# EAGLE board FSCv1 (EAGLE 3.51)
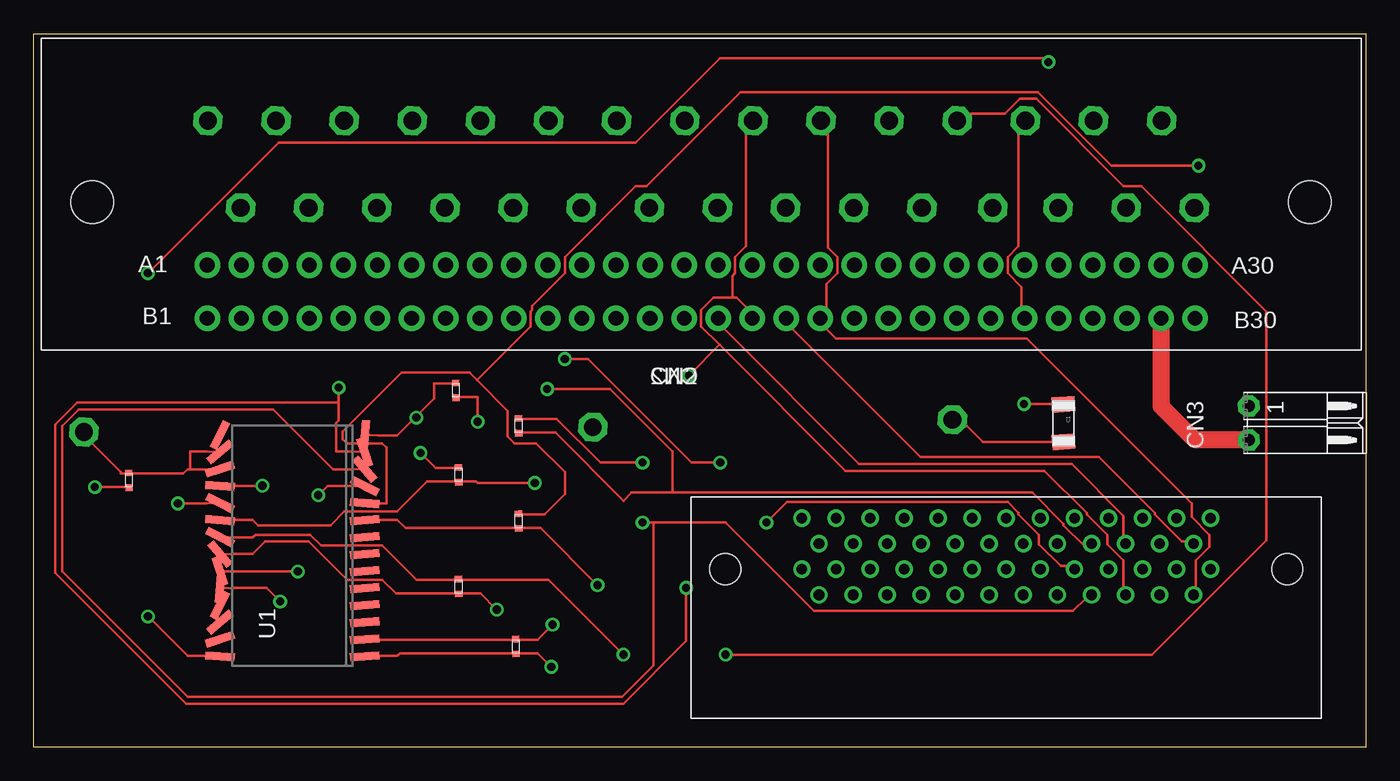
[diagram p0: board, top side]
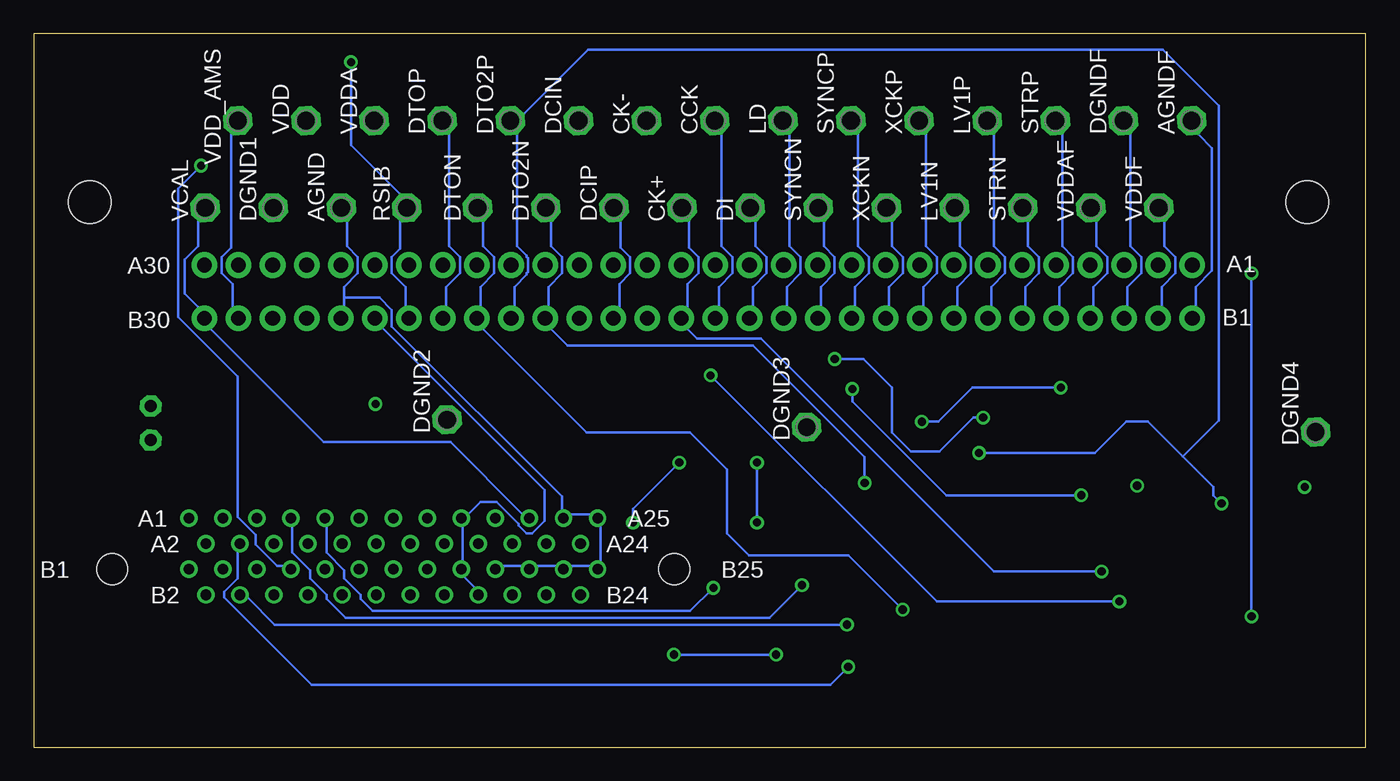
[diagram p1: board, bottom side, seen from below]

Size 99.36 x 53.24 mm. Coordinates in mm from the lower left corner, seen from the top.
Outline: 0,53.24 99.36,53.24 99.36,0 0,0 0,53.24
Copper layers used: Top, Bottom

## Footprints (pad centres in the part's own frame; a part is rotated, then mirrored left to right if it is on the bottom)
-13 = drill 1.321 pad 2.159 octagon:  0,0
06 = smd 1.15 x 1.7 rotated 4.3:  -1.4,0 | smd 1.15 x 1.7 rotated 4.4:  1.4,0
02 = smd 0.5 x 0.55 rotated 4.3:  -0.55,0 | smd 0.5 x 0.55 rotated 4.4:  0.55,0
0LE050 = drill 0.787 pad 1.194 round:  15.24,2.857;  13.97,0.953;  12.7,2.857;  11.43,0.953;  10.16,2.857;  15.24,-0.953;  13.97,-2.857;  12.7,-0.953;  11.43,-2.857;  10.16,-0.953;  8.89,-2.857;  8.89,0.953;  7.62,2.857;  6.35,0.953;  5.08,2.857;  3.81,0.953;  2.54,2.857;  7.62,-0.953;  6.35,-2.857;  5.08,-0.953;  3.81,-2.857;  2.54,-0.953;  1.27,-2.857;  1.27,0.953;  0,2.857;  -1.27,0.953;  -2.54,2.857;  -3.81,0.953;  -5.08,2.857;  0,-0.953;  -1.27,-2.857;  -2.54,-0.953;  -3.81,-2.857;  -5.08,-0.953;  -6.35,-2.857;  -6.35,0.953;  -7.62,2.857;  -8.89,0.953;  -10.16,2.857;  -11.43,0.953;  -12.7,2.857;  -7.62,-0.953;  -8.89,-2.857;  -10.16,-0.953;  -11.43,-2.857;  -12.7,-0.953;  -13.97,-2.857;  -13.97,0.953;  -15.24,2.857;  -15.24,-0.953 | hole 2.311: 20.955,-0.953; -20.955,-0.953
30LP = drill 1.092 pad 1.905 round:  36.83,3.962;  36.83,0;  34.29,3.962;  34.29,0;  31.75,3.962;  31.75,0;  29.21,3.962;  29.21,0;  26.67,3.962;  26.67,0;  24.13,3.962;  24.13,0;  21.59,3.962;  21.59,0;  19.05,3.962;  19.05,0;  16.51,3.962;  16.51,0;  13.97,3.962;  13.97,0;  11.43,3.962;  11.43,0;  8.89,3.962;  8.89,0;  6.35,3.962;  6.35,0;  3.81,3.962;  3.81,0;  1.27,3.962;  1.27,0;  -1.27,3.962;  -1.27,0;  -3.81,3.962;  -3.81,0;  -6.35,3.962;  -6.35,0;  -8.89,3.962;  -8.89,0;  -11.43,3.962;  -11.43,0;  -13.97,3.962;  -13.97,0;  -16.51,3.962;  -16.51,0;  -19.05,3.962;  -19.05,0;  -21.59,3.962;  -21.59,0;  -24.13,3.962;  -24.13,0;  -26.67,3.962;  -26.67,0;  -29.21,3.962;  -29.21,0;  -31.75,3.962;  -31.75,0;  -34.29,3.962;  -34.29,0;  -36.83,3.962;  -36.83,0 | hole 3.175: -45.403,-4.699; 45.403,-4.699
PA = drill 0.914 pad 1.6 octagon:  -1.27,0;  1.27,0
28X = smd 0.6 x 2.2 rotated 4.4:  -6.985,-5.4;  1.905,5.4 | smd 0.6 x 2.2 rotated 71.8:  6.985,-5.4 | smd 0.6 x 2.2 rotated 4.3:  -8.255,-5.4;  3.175,-5.4 | smd 0.6 x 2.2 rotated 4.5:  -5.715,-5.4 | smd 0.6 x 2.2 rotated 4.6:  -4.445,-5.4 | smd 0.6 x 2.2 rotated 94.3:  8.255,-5.4 | smd 0.6 x 2.2 rotated 49.3:  5.715,-5.4 | smd 0.6 x 2.2 rotated 26.8:  4.445,-5.4 | smd 0.6 x 2.2 rotated 4.7:  -1.905,-5.4;  -3.175,-5.4 | smd 0.6 x 2.2 rotated 5:  1.905,-5.4 | smd 0.6 x 2.2 rotated 4.8:  -0.635,-5.4 | smd 0.6 x 2.2 rotated 4.9:  0.635,-5.4 | smd 0.6 x 2.2 rotated 116.8:  8.255,5.4 | smd 0.6 x 2.2 rotated 139.3:  6.985,5.4 | smd 0.6 x 2.2 rotated 161.8:  5.715,5.4 | smd 0.6 x 2.2 rotated 184.3:  4.445,5.4 | smd 0.6 x 2.2 rotated 206.8:  3.175,5.4 | smd 0.6 x 2.2 rotated 26.9:  0.635,5.4 | smd 0.6 x 2.2 rotated 49.4:  -0.635,5.4 | smd 0.6 x 2.2 rotated 71.9:  -1.905,5.4 | smd 0.6 x 2.2 rotated 94.4:  -3.175,5.4 | smd 0.6 x 2.2 rotated 116.9:  -4.445,5.4 | smd 0.6 x 2.2 rotated 139.4:  -5.715,5.4 | smd 0.6 x 2.2 rotated 161.9:  -6.985,5.4 | smd 0.6 x 2.2 rotated 184.4:  -8.255,5.4

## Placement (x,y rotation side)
AGND  B1,27  [-13]  76.4,40.23 90 bottom
AGNDF  B1,27  [-13]  13,46.74 90 bottom
C1  4.7  [06]  76.81,24.18 270 top
C2  0.1  [02]  7.11,19.91 90 top
CCK  B1,27  [-13]  48.56,46.74 90 bottom
CK+  B1,27  [-13]  51,40.23 90 bottom
CK-  B1,27  [-13]  53.64,46.74 90 bottom
CN1  P50LE050  [0LE050]  72.54,14.22 0 top
CN2  EZC30DRAS  [30LP]  49.78,35.97 180 top
CN3  AMS PWR  [PA]  90.63,24.18 270 top
DCIN  B1,27  [-13]  58.72,46.74 90 bottom
DCIP  B1,27  [-13]  56.08,40.23 90 bottom
DGND1  B1,27  [-13]  81.48,40.23 90 bottom
DGND2  B1,27  [-13]  68.53,24.43 90 bottom
DGND3  B1,27  [-13]  41.71,23.88 90 bottom
DGND4  B1,27  [-13]  3.76,23.52 90 bottom
DGNDF  B1,27  [-13]  18.08,46.74 90 bottom
DI  B1,27  [-13]  45.92,40.23 90 bottom
DTO2N  B1,27  [-13]  61.16,40.23 90 bottom
DTO2P  B1,27  [-13]  63.8,46.74 90 bottom
DTON  B1,27  [-13]  66.24,40.23 90 bottom
DTOP  B1,27  [-13]  68.88,46.74 90 bottom
LD  B1,27  [-13]  43.48,46.74 90 bottom
LV1N  B1,27  [-13]  30.68,40.23 90 bottom
LV1P  B1,27  [-13]  28.24,46.74 90 bottom
R1  110  [02]  35.97,7.52 270 top
R2  110  [02]  31.7,11.99 270 top
R3  110  [02]  31.7,20.32 270 top
R4  110  [02]  31.5,26.62 90 top
R5  110  [02]  36.17,23.98 90 top
R6  110  [02]  36.17,16.87 90 top
RSIB  B1,27  [-13]  71.53,40.23 90 bottom
STRN  B1,27  [-13]  25.6,40.23 90 bottom
STRP  B1,27  [-13]  23.16,46.74 90 bottom
SYNCN  B1,27  [-13]  40.84,40.23 90 bottom
SYNCP  B1,27  [-13]  38.4,46.74 90 bottom
U1  IBM_BUF  [28X]  19.3,15.04 90 top
VCAL  B1,27  [-13]  86.56,40.23 90 bottom
VDD  B1,27  [-13]  79.04,46.74 90 bottom
VDD_AMS  B1,27  [-13]  84.12,46.74 90 bottom
VDDA  B1,27  [-13]  73.96,46.74 90 bottom
VDDAF  B1,27  [-13]  20.52,40.23 90 bottom
VDDF  B1,27  [-13]  15.44,40.23 90 bottom
XCKN  B1,27  [-13]  35.76,40.23 90 bottom
XCKP  B1,27  [-13]  33.32,46.74 90 bottom

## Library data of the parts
AGND AGNDF CCK CK+ CK- DCIN DCIP DGND1-DGND4 DGNDF DI DTO2N DTO2P DTON DTOP LD LV1N LV1P RSIB STRN STRP SYNCN SYNCP VCAL VDD VDD_AMS VDDA VDDAF VDDF XCKN XCKP = TESTPAD
C1 C2 R1-R6 = 1X
CN1 CN2 = CONNECT
CN3 = CONQUICK
U1 = IPC-SMD

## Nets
AGND: AGND. CN1. CN2.
CCK: CCK. CN2.
CK+: CK+. CN1. CN2. U1.
CK-: CK-. CN1. CN2. U1.
CKR+: CN1. R6. U1.
CKR-: CN1. R6. U1.
DCIN: CN1. CN2. DCIN.
DCIP: CN1. CN2. DCIP.
DGND: C1. C2. CN1. CN2. CN3. DGND1. DGND2. DGND3. DGND4. U1.
DI: CN2. DI.
DTO2+: CN1. R4. U1.
DTO2-: CN1. R4. U1.
DTO2N: CN2. DTO2N. R3. U1.
DTO2P: CN2. DTO2P. R3. U1.
DTO+: CN1. R5. U1.
DTO-: CN1. R5. U1.
DTON: CN2. DTON. R2. U1.
DTOP: CN2. DTOP. R2. U1.
LD: CN2. LD.
N$1: CN2. XCKP.
N$2: CN2. LV1N.
N$3: CN2. LV1P.
N$4: CN2. STRN.
N$5: CN2. XCKN.
N$6: CN2. STRP.
N$9: CN2. VDDAF.
N$10: CN2. DGNDF.
N$11: CN2. SYNCP.
N$12: CN2. VDDF.
N$13: AGNDF. CN2.
RSIB: CN2. RSIB. U1.
RSTB+: CN1. R1. U1.
RSTB-: CN1. R1. U1.
SYNCN: CN2. SYNCN.
VCAL: CN1. CN2. VCAL.
VDD: C1. C2. CN1. CN2. U1. VDD.
VDD_AMS: CN2. CN3. VDD_AMS.
VDDA: CN1. CN2. VDDA.

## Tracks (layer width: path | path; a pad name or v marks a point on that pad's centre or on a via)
AGND
  Bottom 0.203: 76.2,33.53 76.2,34.34 75.18,35.36 75.18,36.58 76,37.39 76,39.22 AGND. | 76.2,33.53 76.2,32.92 76.45,32 | 64.92,13.27 64.41,13.51 62.89,13.51 62.38,13.27 61.87,13.51 60.35,13.51 59.84,13.27 59.33,13.51 57.81,13.51 CN1. 57.1,13.82 57.1,16.56 57.3,17.08 57.81,17.37 59.33,17.37 59.84,17.08 59.94,17.68 59.94,18.69 72.64,31.39 72.64,32.61 73.56,33.53 76.2,33.53
CCK
  Bottom 0.203: 48.51,32 48.26,32.92 48.26,34.34 47.24,35.36 47.24,36.58 48.06,37.39 48.06,45.72 CCK.
CK+  (via drill 0.61 pad 1.02)
  Top 0.203: 81.43,15.18 81.28,15.75 81.28,17.27 77.42,21.13 61.57,21.13 51.51,31.19 51.05,32 | v19.71,13.11 14.94,13.11 13.9,13.13
  Bottom 0.203: v19.71,13.11 27.74,13.11 45.11,30.48 49.89,30.48 50.6,31.19 51.05,32 50.6,32.82 50.6,34.54 49.78,35.36 49.78,36.58 50.49,37.29 50.49,39.22 CK+.
CK-  (via drill 0.61 pad 1.02)
  Top 0.203: 51.16,30.02 49.78,31.39 49.78,32.61 50.7,33.53 52.12,33.53 | 51.16,30.02 60.55,20.62 75.39,20.62 78.54,17.48 78.54,17.37 80.06,15.85 80.06,15.14 81.28,13.92 81.28,11.89 81.43,11.37 | 52.12,33.53 52.43,33.53 53.14,32.82 53.59,32 | v18.39,10.87 17.37,11.89 14.94,11.89 13.9,11.86 | v48.87,27.74 51.16,30.02 | CK-. 53.14,45.72 53.14,37.39 52.32,36.58 52.32,35.36 52.12,35.15 52.12,33.53
  Bottom 0.203: v18.39,10.87 32,10.87 v48.87,27.74
CKR+  (via drill 0.61 pad 1.02)
  Top 0.203: 24.7,16.94 25.7,16.97 27.13,16.97 27.74,16.36 35.97,16.36 36.17,16.32 36.37,16.36 37.8,16.36 v42.06,12.09
  Bottom 0.203: v42.06,12.09 44.5,9.65 76.1,9.65 77.52,11.07 77.52,11.38 78.74,12.6 78.74,13.21 80.06,14.53 80.06,16.56 80.16,17.08
CKR-  (via drill 0.61 pad 1.02)
  Top 0.203: 33.07,27.38 32.51,27.94 27.43,27.94 23.06,23.57 23.06,22.96 23.37,22.66 26.01,22.66 26.31,22.35 26.31,18.19 25.7,18.19 24.7,18.21 | 33.07,27.38 35.36,25.09 35.36,23.16 35.87,22.66 37.49,22.66 39.62,20.52 39.62,18.9 38.1,17.37 36.37,17.37 R6. | v86.87,43.38 80.37,43.38 74.88,48.87 52.73,48.87 45.72,41.86 44.91,41.86 39.62,36.58 39.62,35.36 37.19,32.92 37.19,32.61 37.08,32.51 37.08,31.39 33.07,27.38
  Bottom 0.203: v86.87,43.38 88.59,41.66 88.59,32.11 84.12,27.64 84.12,17.17 82.8,15.85 82.8,15.14 81.18,13.51 80.67,13.51 80.16,13.27
DCIN
  Top 0.203: 86.51,11.37 86.67,11.89 86.67,13.92 87.68,14.94 87.68,15.85 86.36,17.17 86.36,18.19 74.07,30.48 59.84,30.48 59.13,31.19 58.67,32 59.13,32.82 59.13,34.54 59.94,35.36 59.94,36.58 59.23,37.29 59.23,45.72 DCIN.
DCIP
  Top 0.203: 86.51,15.18 85.95,15.34 85.65,15.34 83.62,17.37 83.62,17.48 79.45,21.64 66.14,21.64 56.59,31.19 56.13,32
  Bottom 0.203: DCIP. 55.58,39.22 55.58,37.29 54.86,36.58 54.86,35.36 55.68,34.54 55.68,32.82 56.13,32
DGND
  Top 0.203: 11.68,20.73 12.9,20.73 13.9,20.75 | 11.68,20.73 11.48,20.73 11.18,20.42 7.32,20.42 C2. 6.91,20.42 6.5,20.42 6.5,20.52 4.37,22.66 DGND4. | 13.9,22.02 12.9,22.05 11.68,22.05 11.68,20.73 | C1. 76,22.76 70.81,22.76 69.6,23.98 DGND2.
DI
  Bottom 0.203: 45.97,32 45.72,32.92 45.72,34.34 44.7,35.36 44.7,36.58 45.52,37.39 45.52,39.22 DI.
DTO2+  (via drill 0.61 pad 1.02)
  Top 0.203: v33.12,24.28 33.12,26.11 31.7,26.11 31.5,26.07 | 22.76,25.7 22.76,24.38 22.55,24.18 22.55,22.05 23.67,22.05 24.7,22.02 | 22.76,25.7 v22.76,26.82 | v48.67,11.89 48.67,7.92 43.99,3.25 11.38,3.25 1.63,13.01 1.63,24.08 3.25,25.7 22.76,25.7
  Bottom 0.203: v33.12,24.28 31.9,24.28 29.36,26.82 v22.76,26.82 | v48.67,11.89 50.39,10.16 74.07,10.16 74.98,11.07 74.98,11.38 76.2,12.6 76.2,13.21 77.52,14.53 77.52,16.56 77.62,17.08
DTO2-  (via drill 0.61 pad 1.02)
  Top 0.203: 28.5,24.64 27.13,23.27 25.7,23.27 24.7,23.29 | 28.5,24.64 29.87,26.01 29.87,27.13 31.29,27.13 R4. | v54.66,16.76 56.19,18.29 72.64,18.29 73.46,17.48 73.46,17.37 74.98,15.85 74.98,15.14 76.61,13.51 77.11,13.51 77.62,13.27 | v51.21,21.23 49.07,21.23 41.35,28.96 v39.62,28.96 | 28.5,24.64 v28.55,24.59
  Bottom 0.203: v54.66,16.76 54.66,17.78 v51.21,21.23 | v39.62,28.96 37.49,28.96 35.36,26.82 35.36,23.47 33.93,22.05 31.8,22.05 29.26,24.59 v28.55,24.59
DTO2N  (via drill 0.61 pad 1.02)
  Top 0.203: 13.9,16.94 14.94,16.97 16.36,16.97 16.76,16.56 22.15,16.56 23.16,17.58 27.13,17.58 29.36,19.81 31.5,19.81 R3. 31.9,19.81 33.02,19.81 33.12,19.71 v37.39,19.71
  Bottom 0.203: DTO2N. 60.76,39.22 60.76,37.39 59.94,36.58 59.94,35.36 60.96,34.34 60.96,32.92 61.21,32 60.76,31.19 59.54,29.97 45.72,29.97 37.39,21.64 v37.39,19.71
DTO2P  (via drill 0.61 pad 1.02)
  Top 0.203: v28.85,21.95 29.97,20.83 31.5,20.83 31.7,20.87 | v10.77,18.19 12.9,18.19 13.9,18.21
  Bottom 0.203: 63.75,32 63.5,32.92 63.5,34.34 62.59,35.26 62.59,35.36 62.48,35.46 62.48,36.47 62.59,36.58 62.59,36.68 63.3,37.39 63.3,45.72 DTO2P. 62.79,47.24 58.01,52.02 15.14,52.02 10.97,47.85 10.97,24.38 13.66,21.69 | v28.85,21.95 20.22,21.95 17.88,24.28 16.26,24.28 13.66,21.69 | 13.66,21.69 11.38,19.41 11.38,18.8 v10.77,18.19
DTO+  (via drill 0.61 pad 1.02)
  Top 0.203: 47.65,19 74.47,19 76.81,16.66 76.81,16.56 78.33,15.04 78.89,15.18 | 47.65,19 44.6,19 43.99,18.39 38.91,23.47 36.37,23.47 36.17,23.43 | v21.23,18.8 21.95,19.51 23.67,19.51 24.7,19.48 | v38.3,26.72 42.98,26.72 47.65,22.05 47.65,19
  Bottom 0.203: v21.23,18.8 31.29,18.8 38.3,25.81 v38.3,26.72
DTO-  (via drill 0.61 pad 1.02)
  Top 0.203: v45.41,21.23 42.27,21.23 39.01,24.49 36.37,24.49 R5. | 46.23,16.76 51.61,16.76 58.22,10.16 77.52,10.16 78.44,11.07 78.89,11.37 | 46.23,16.76 v45.41,16.76 | 24.7,20.75 23.67,20.73 22.35,20.73 17.88,25.2 3.35,25.2 2.13,23.98 2.13,13.11 11.48,3.76 43.89,3.76 46.23,6.1 46.23,16.76
  Bottom 0.203: v45.41,16.76 v45.41,21.23
DTON  (via drill 0.61 pad 1.02)
  Top 0.203: 13.9,14.4 14.94,14.43 16.36,14.43 17.27,15.34 20.52,15.34 23.37,12.5 26.01,12.5 27.03,11.48 31.5,11.48 R2. 31.9,11.48 33.33,11.48 v34.54,10.26
  Bottom 0.203: DTON. 65.84,39.22 65.84,37.39 65.02,36.58 65.02,35.36 66.04,34.34 66.04,32.92 66.29,32 65.84,31.19 58.12,23.47 50.39,23.47 47.65,20.73 47.65,15.95 46.02,14.33 38.61,14.33 v34.54,10.26
DTOP  (via drill 0.61 pad 1.02)
  Top 0.203: 13.9,15.67 14.94,15.65 16.36,15.65 16.56,15.85 20.62,15.85 21.44,15.04 26.01,15.04 28.55,12.5 31.5,12.5 31.7,12.54 31.9,12.5 38.41,12.5 v43.99,6.91 | v51.61,6.91 83.41,6.91 91.95,15.44 91.95,32.51 82.6,41.86 81.28,41.86 74.78,48.36 73.56,48.36 72.44,47.24 69.9,47.24 DTOP.
  Bottom 0.203: 68.83,32 68.58,32.92 68.58,34.34 67.56,35.36 67.56,36.58 68.38,37.39 68.38,45.72 DTOP. | v43.99,6.91 v51.61,6.91
LD
  Bottom 0.203: 43.43,32 43.18,32.92 43.18,34.34 42.16,35.36 42.16,36.58 42.98,37.39 42.98,45.72 LD.
N$1
  Bottom 0.203: 33.27,32 33.02,32.92 33.02,34.34 32,35.36 32,36.58 32.82,37.39 32.82,45.72 XCKP.
N$2
  Bottom 0.203: 30.73,32 30.48,32.92 30.48,34.34 29.46,35.36 29.46,36.58 30.28,37.39 30.28,39.22 LV1N.
N$3
  Bottom 0.203: 28.19,32 27.94,32.92 27.94,34.34 26.92,35.36 26.92,36.58 27.74,37.39 27.74,45.72 LV1P.
N$4
  Bottom 0.203: 25.65,32 25.4,32.92 25.4,34.34 24.38,35.36 24.38,36.58 25.2,37.39 25.2,39.22 STRN.
N$5
  Bottom 0.203: 35.81,32 35.56,32.92 35.56,34.34 34.54,35.36 34.54,36.58 35.36,37.39 35.36,39.22 XCKN.
N$6
  Bottom 0.203: 23.11,32 22.86,32.92 22.86,34.34 21.84,35.36 21.84,36.58 22.66,37.39 22.66,45.72 STRP.
N$9
  Bottom 0.203: 20.57,32 20.32,32.92 20.32,34.34 19.3,35.36 19.3,36.58 20.12,37.39 20.12,39.22 VDDAF.
N$10
  Bottom 0.203: 18.03,32 17.78,32.92 17.78,34.34 16.76,35.36 16.76,36.58 17.58,37.39 17.58,45.72 DGNDF.
N$11
  Bottom 0.203: 38.35,32 38.1,32.92 38.1,34.34 37.08,35.36 37.08,36.58 37.9,37.39 37.9,45.72 SYNCP.
N$12
  Bottom 0.203: 15.49,32 15.24,32.92 15.24,34.34 14.22,35.36 14.22,36.58 15.04,37.39 15.04,39.22 VDDF.
N$13
  Bottom 0.203: 12.95,32 12.7,32.92 12.7,34.34 11.48,35.56 11.48,44.7 12.5,45.72 AGNDF.
RSIB  (via drill 0.61 pad 1.02)
  Top 0.203: v8.53,9.75 11.48,6.81 12.9,6.81 U1. | v8.53,35.36 18.29,45.11 44.91,45.11 51.21,51.41 75.39,51.41 v75.69,51.1
  Bottom 0.203: v8.53,35.36 v8.53,9.75 | v75.69,51.1 75.69,44.91 72.03,41.25 RSIB. 72.03,39.22 72.03,37.19 72.64,36.58 72.64,35.36 71.63,34.34 71.63,32.92 71.37,32
RSTB+  (via drill 0.61 pad 1.02)
  Top 0.203: 24.7,6.78 25.7,6.81 27.13,6.81 27.33,7.01 35.76,7.01 R1. 36.17,7.01 37.59,7.01 v38.61,5.99
  Bottom 0.203: v38.61,5.99 39.93,4.67 78.64,4.67 85.14,11.18 85.14,11.58 84.12,12.6 84.12,14.63 83.97,15.18
RSTB-  (via drill 0.61 pad 1.02)
  Top 0.203: 24.7,8.05 25.7,8.03 35.76,8.03 35.97,8.07 36.17,8.03 37.59,8.03 v38.71,9.14
  Bottom 0.203: v38.71,9.14 81.38,9.14 83.41,11.18 83.97,11.37
SYNCN
  Bottom 0.203: 40.89,32 40.64,32.92 40.64,34.34 39.62,35.36 39.62,36.58 40.44,37.39 40.44,39.22 SYNCN.
VCAL
  Bottom 0.203: 62.38,17.08 62.89,17.37 68.28,22.76 77.72,22.76 86.16,31.19 86.61,32 87.07,32.82 88.09,33.83 88.09,36.37 87.07,37.39 87.07,39.22 VCAL.
VDD  (via drill 0.61 pad 1.02)
  Top 0.203: v4.57,19.41 6.91,19.41 7.11,19.36 | v17.07,19.51 14.94,19.51 13.9,19.48 | v73.86,25.6 76,25.6 76.81,25.58
VDD_AMS
  Top 1.27: 84.07,32 84.07,25.45 86.56,22.96 90.42,22.96 90.47,22.91 CN3.
  Bottom 0.203: VDD_AMS. 84.63,45.72 84.63,37.29 85.34,36.58 85.34,35.36 84.53,34.54 84.53,32.82 84.07,32
VDDA
  Top 0.203: 73.91,32 73.66,32.92 73.66,34.34 72.64,35.36 72.64,36.58 73.46,37.39 73.46,45.72 VDDA.
  Bottom 0.203: 66.19,11.37 66.45,11.89 67.36,12.8 67.46,13.27 67.36,13.82 67.36,16.56 67.46,17.08 66.95,17.37 66.04,18.29 64.82,18.29 63.2,16.66 63.2,16.56 62.59,15.95 62.18,15.95 61.27,16.87 61.27,19.2 73.36,31.29 73.91,32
